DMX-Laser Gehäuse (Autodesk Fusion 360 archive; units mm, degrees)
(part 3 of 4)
sketch "Skizze25" plane through (45, 0, 0) normal (-1, 0, 0) x axis (0, -1, 0)
  line L1 (3, 60) -> (40, 60)
  line L2 (3, -2) -> (3, 60)
  line L3 (58, -2) -> (3, -2)
  line L4 (58, 8) -> (58, -2)
  line L5 (57, 8) -> (58, 8)
  line L6 (45, 55) -> (45, 20)
  line L7 (14.5116, 11) -> (14.5116, 15)
  line L8 (14.0559, 11) -> (14.5116, 11)
  line L9 (14.0559, 11.3656) -> (14.0559, 11)
  curve K1 (13.2456, 10.9345) -> (14.0559, 11.3656)
  curve K2 (12.6085, 11.1255) -> (13.2456, 10.9345)
  curve K3 (12.1583, 11.6589) -> (12.6085, 11.1255)
  curve K4 (11.9986, 12.4461) -> (12.1583, 11.6589)
  curve K5 (12.1432, 13.2333) -> (11.9986, 12.4461)
  curve K6 (12.5771, 13.7749) -> (12.1432, 13.2333)
  curve K7 (13.2237, 13.9632) -> (12.5771, 13.7749)
  curve K8 (13.6903, 13.8527) -> (13.2237, 13.9632)
  curve K9 (14.0232, 13.5648) -> (13.6903, 13.8527)
  line L10 (14.0232, 15) -> (14.0232, 13.5648)
  line L11 (14.5116, 15) -> (14.0232, 15)
  line L12 (19.4202, 12.5962) -> (16.779, 12.5962)
  line L13 (19.4202, 12.1378) -> (19.4202, 12.5962)
  line L14 (16.779, 12.1378) -> (19.4202, 12.1378)
  line L15 (16.779, 12.5962) -> (16.779, 12.1378)
  line L16 (23.3656, 15.0164) -> (23.0491, 15.0164)
  line L17 (23.3656, 11) -> (23.3656, 15.0164)
  line L18 (22.8745, 11) -> (23.3656, 11)
  line L19 (22.8745, 14.1296) -> (22.8745, 11)
  curve K10 (22.4093, 13.7913) -> (22.8745, 14.1296)
  curve K11 (21.8922, 13.5375) -> (22.4093, 13.7913)
  line L20 (21.8922, 14.0123) -> (21.8922, 13.5375)
  curve K12 (22.6126, 14.4816) -> (21.8922, 14.0123)
  curve K13 (23.0491, 15.0164) -> (22.6126, 14.4816)
  line L21 (29.9113, 11) -> (29.9113, 12.5034)
  line L22 (29.4202, 11) -> (29.9113, 11)
  line L23 (29.4202, 13.8977) -> (29.4202, 11)
  line L24 (29.8595, 13.8977) -> (29.4202, 13.8977)
  line L25 (29.8595, 13.4911) -> (29.8595, 13.8977)
  curve K14 (30.2224, 13.8336) -> (29.8595, 13.4911)
  curve K15 (30.7381, 13.9632) -> (30.2224, 13.8336)
  curve K16 (31.266, 13.8295) -> (30.7381, 13.9632)
  curve K17 (31.5566, 13.4557) -> (31.266, 13.8295)
  curve K18 (32.4516, 13.9632) -> (31.5566, 13.4557)
  curve K19 (33.1146, 13.7244) -> (32.4516, 13.9632)
  curve K20 (33.3465, 12.9891) -> (33.1146, 13.7244)
  line L26 (33.3465, 11) -> (33.3465, 12.9891)
  line L27 (32.8581, 11) -> (33.3465, 11)
  line L28 (32.8581, 12.8254) -> (32.8581, 11)
  curve K21 (32.8104, 13.2497) -> (32.8581, 12.8254)
  curve K22 (32.6371, 13.4584) -> (32.8104, 13.2497)
  curve K23 (32.3424, 13.5375) -> (32.6371, 13.4584)
  curve K24 (31.8349, 13.3342) -> (32.3424, 13.5375)
  curve K25 (31.633, 12.6835) -> (31.8349, 13.3342)
  line L29 (31.633, 11) -> (31.633, 12.6835)
  line L30 (31.1419, 11) -> (31.633, 11)
  line L31 (31.1419, 12.8827) -> (31.1419, 11)
  curve K26 (31.0218, 13.3738) -> (31.1419, 12.8827)
  curve K27 (30.6289, 13.5375) -> (31.0218, 13.3738)
  curve K28 (30.2456, 13.4284) -> (30.6289, 13.5375)
  curve K29 (29.9905, 13.1091) -> (30.2456, 13.4284)
  curve K30 (29.9113, 12.5034) -> (29.9905, 13.1091)
  curve K31 (25.0177, 11.2374) -> (25.9086, 10.9318)
  curve K32 (24.6235, 12.0477) -> (25.0177, 11.2374)
  line L32 (25.1392, 12.0914) -> (24.6235, 12.0477)
  curve K33 (25.4052, 11.5252) -> (25.1392, 12.0914)
  curve K34 (25.9086, 11.3356) -> (25.4052, 11.5252)
  curve K35 (26.5089, 11.603) -> (25.9086, 11.3356)
  curve K36 (26.7544, 12.3124) -> (26.5089, 11.603)
  curve K37 (26.5184, 12.9754) -> (26.7544, 12.3124)
  curve K38 (25.9004, 13.2183) -> (26.5184, 12.9754)
  curve K39 (25.472, 13.1105) -> (25.9004, 13.2183)
  curve K40 (25.1719, 12.8308) -> (25.472, 13.1105)
  line L33 (24.7108, 12.8909) -> (25.1719, 12.8308)
  line L34 (25.0982, 14.9454) -> (24.7108, 12.8909)
  line L35 (27.0873, 14.9454) -> (25.0982, 14.9454)
  line L36 (27.0873, 14.4761) -> (27.0873, 14.9454)
  line L37 (25.4911, 14.4761) -> (27.0873, 14.4761)
  line L38 (25.2756, 13.4011) -> (25.4911, 14.4761)
  curve K41 (26.0314, 13.6521) -> (25.2756, 13.4011)
  curve K42 (26.9154, 13.2892) -> (26.0314, 13.6521)
  curve K43 (27.2756, 12.3561) -> (26.9154, 13.2892)
  curve K44 (26.9591, 11.4175) -> (27.2756, 12.3561)
  curve K45 (25.9086, 10.9318) -> (26.9591, 11.4175)
  line L39 (34.5662, 11) -> (34.5662, 12.5034)
  line L40 (34.075, 11) -> (34.5662, 11)
  line L41 (34.075, 13.8977) -> (34.075, 11)
  line L42 (34.5143, 13.8977) -> (34.075, 13.8977)
  line L43 (34.5143, 13.4911) -> (34.5143, 13.8977)
  curve K46 (34.8772, 13.8336) -> (34.5143, 13.4911)
  curve K47 (35.3929, 13.9632) -> (34.8772, 13.8336)
  curve K48 (35.9209, 13.8295) -> (35.3929, 13.9632)
  curve K49 (36.2115, 13.4557) -> (35.9209, 13.8295)
  curve K50 (37.1064, 13.9632) -> (36.2115, 13.4557)
  curve K51 (37.7694, 13.7244) -> (37.1064, 13.9632)
  curve K52 (38.0014, 12.9891) -> (37.7694, 13.7244)
  line L44 (38.0014, 11) -> (38.0014, 12.9891)
  line L45 (37.513, 11) -> (38.0014, 11)
  line L46 (37.513, 12.8254) -> (37.513, 11)
  curve K53 (37.4652, 13.2497) -> (37.513, 12.8254)
  curve K54 (37.292, 13.4584) -> (37.4652, 13.2497)
  curve K55 (36.9973, 13.5375) -> (37.292, 13.4584)
  curve K56 (36.4898, 13.3342) -> (36.9973, 13.5375)
  curve K57 (36.2879, 12.6835) -> (36.4898, 13.3342)
  line L47 (36.2879, 11) -> (36.2879, 12.6835)
  line L48 (35.7967, 11) -> (36.2879, 11)
  line L49 (35.7967, 12.8827) -> (35.7967, 11)
  curve K58 (35.6767, 13.3738) -> (35.7967, 12.8827)
  curve K59 (35.2838, 13.5375) -> (35.6767, 13.3738)
  curve K60 (34.9004, 13.4284) -> (35.2838, 13.5375)
  curve K61 (34.6453, 13.1091) -> (34.9004, 13.4284)
  curve K62 (34.5662, 12.5034) -> (34.6453, 13.1091)
  line L50 (19.4202, 13.8104) -> (16.779, 13.8104)
  line L51 (19.4202, 13.352) -> (19.4202, 13.8104)
  line L52 (16.779, 13.352) -> (19.4202, 13.352)
  line L53 (16.779, 13.8104) -> (16.779, 13.352)
  line L54 (45.5, 37.55) -> (22.15, 37.55)
  line L55 (33.175, 39.55) -> (33.175, 37.55)
  line L56 (33.025, 39.55) -> (33.175, 39.55)
  line L57 (33.025, 48.45) -> (33.025, 39.55)
  line L58 (52.825, 39.55) -> (52.825, 48.45)
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  point P6 (22.15, 37.55)
  point P126 (22.15, 37.55)
  point P128 (33.175, 37.55)
  point P129 (33.175, 39.55)
  point P130 (33.025, 39.55)
  point P131 (33.025, 48.45)
  point P132 (52.825, 48.45)
  point P133 (52.825, 48.45)
  point P135 (33.025, 39.55)
  point P136 (38.175, 48.45)
  point P137 (47.675, 48.45)
  point P142 (52.825, 48.45)
  point P144 (33.025, 51.35)
  coincident P6 P126
  perpendicular L6 L54
  coincident L54 P128
  perpendicular L54 L55
  perpendicular L55 L56
  perpendicular L56 L57
  vertical L58
  dimension "d132" distance P128 P129 = 2
  dimension "d133" distance P129 P130 = 0.15
  dimension "d134" distance P130 P131 = 8.9
  dimension "d135" distance P131 P132 = 19.8
  dimension "d136" distance P131 P133 = 19.8
  dimension "d137" distance P131 P135 = 8.9
  dimension "d138" distance P131 P136 = 5.15
  dimension "d139" distance P133 P137 = 5.15
  dimension "d140" diameter = 2.4
  dimension "d141" diameter = 2.4
  dimension "d142" distance P131 P142 = 19.8
  dimension "d143" distance P131 P144 = 2.9
sketch "Skizze26" plane through (0, -45, 0) normal (0, -1, 0) x axis (1, 0, 0)
  line L1 (45, 55) -> (55, 55)
  line L2 (45, 20) -> (45, 55)
  line L3 (55, 20) -> (45, 20)
  line L4 (55, 55) -> (55, 20)
  line L5 (55, 54) -> (45, 54)
  line L6 (55, 43) -> (55, 54)
  line L7 (45, 43) -> (55, 43)
  line L8 (45, 54) -> (45, 43)
  point P8 (55, 43)
  point P6 (45, 54)
  horizontal L5
  vertical L6
  horizontal L7
  vertical L8
  coincident L4 P8
  coincident L2 P6
extrude "Extrusion38" add sketch "Skizze26" profile of L2 L4 L5 L6 L7 L8 along normal blind 9
extrude "Extrusion39" new body sketch "Skizze25" along normal blind 1.8
move "Verschieben6"
extrude "Extrusion40" cut of existing geometry blind -3
fillet "Abrundung8" radius 2 3
copy_paste_bodies "Körper kopieren/einfügen3"
move "Verschieben7"
move "Verschieben8"
move_face "Fläche verschieben"
move "Verschieben9" RotateAngle 180
move "Verschieben10" RotateAngle -90
copy_paste_bodies "Körper kopieren/einfügen4"
move "Verschieben11"
sketch "Skizze27" plane through (55, 0, 0) normal (1, 0, 0) x axis (0, 1, 0)
  line L1 (-51, 43) -> (-51, 54)
  line L2 (-48, 43) -> (-51, 43)
  line L3 (-45, 20) -> (-45, 40)
  line L4 (-58, 8) -> (-57, 8)
  line L5 (-58, -2) -> (-58, 8)
  line L6 (-43.3405, -2) -> (-58, -2)
  line L7 (-43.3405, 16.4) -> (-43.3405, -2)
  line L8 (-1, 16.4) -> (-43.3405, 16.4)
  line L9 (-1, 30) -> (-1, 16.4)
  line L10 (0.8579, 30) -> (-1, 30)
  line L11 (0.8579, 20) -> (0.8579, 30)
  line L12 (10, 20) -> (0.8579, 20)
  line L13 (10, 45) -> (10, 20)
  line L14 (0, 45) -> (10, 45)
  line L15 (0, 60) -> (0, 45)
  line L16 (-40, 60) -> (0, 60)
  line L17 (-51, 54) -> (-46.9282, 54)
  circle C1 centre (-22.15, 37.55) radius 11.025
  circle C2 centre (-6.65, 22.05) radius 2
  circle C3 centre (-37.65, 53.05) radius 2
  circle C4 centre (-6.65, 53.05) radius 2
  circle C5 centre (-37.65, 22.05) radius 2
  arc A1 centre (-48, 40) radius 3 clockwise from (-48, 43) to (-45, 40)
  arc A2 centre (-57, 20) radius 12 clockwise from (-45, 20) to (-57, 8)
  arc A3 centre (-40, 55) radius 5 clockwise from (-44.9487, 55.7143) to (-40, 60)
  arc A4 centre (-46.9282, 56) radius 2 clockwise from (-44.9487, 55.7143) to (-46.9282, 54)
  circle C6 centre (-37.65, 53.05) radius 2
  circle C7 centre (-37.65, 53.05) radius 1.55
  circle C8 centre (-6.65, 53.05) radius 2
  circle C9 centre (-6.65, 53.05) radius 1.55
  circle C10 centre (-37.65, 22.05) radius 2
  circle C11 centre (-37.65, 22.05) radius 1.55
  circle C12 centre (-6.65, 22.05) radius 2
  circle C13 centre (-6.65, 22.05) radius 1.55
  concentric C3 C6
  concentric C3 C7
  concentric C4 C8
  concentric C4 C9
  concentric C5 C10
  concentric C5 C11
  concentric C2 C12
  concentric C2 C13
  dimension "d156" diameter C6 = 4
  dimension "d157" diameter C7 = 3.1
  dimension "d158" diameter C8 = 4
  dimension "d159" diameter C9 = 3.1
  dimension "d160" diameter C10 = 4
  dimension "d161" diameter C11 = 3.1
  dimension "d162" diameter C12 = 4
  dimension "d163" diameter C13 = 3.1
extrude "Extrusion41" add sketch "Skizze27" profile of C2 C3 C4 C5 C6 C7 C8 C9 C10 C11 C12 C13 against normal blind 10
sketch "Skizze28" plane through (0, 10, 0) normal (0, 1, 0) x axis (-1, 0, 0)
  line L1 (-45.18, 30) -> (-45.18, -2)
  line L2 (-43.3, 30) -> (-45.18, 30)
  line L3 (-43.3, 1.4) -> (-43.3, 30)
  line L4 (-1, 1.4) -> (-43.3, 1.4)
  line L5 (-1, -2) -> (-1, 1.4)
  line L6 (13, -2) -> (-1, -2)
  line L7 (13, 8) -> (13, -2)
  line L8 (12, 8) -> (13, 8)
  line L9 (0, 41.3962) -> (0, 20)
  line L10 (-45, 60) -> (-3.4189, 46.1396)
  line L11 (-55, 60) -> (-45, 60)
  line L12 (-55, 45) -> (-55, 60)
  line L13 (-55, 20) -> (-55, 45)
  line L14 (-45.8579, 20) -> (-55, 20)
  line L15 (-45.8579, 8) -> (-45.8579, 20)
  line L16 (-45.8579, -2) -> (-45.8579, 8)
  line L17 (-45.18, -2) -> (-45.8579, -2)
  arc A1 centre (12, 20) radius 12 clockwise from (12, 8) to (0, 20)
  arc A2 centre (-5, 41.3962) radius 5 clockwise from (-3.4189, 46.1396) to (0, 41.3962)
  circle C1 centre (-37.65, 7.05) radius 2
  circle C2 centre (-6.65, 38.05) radius 2
  circle C3 centre (-37.65, 38.05) radius 2
  circle C4 centre (-6.65, 7.05) radius 2
  circle C5 centre (-22.15, 22.55) radius 11.025
  circle C6 centre (-37.65, 38.05) radius 2
  circle C7 centre (-37.65, 38.05) radius 1.55
  circle C8 centre (-6.65, 38.05) radius 2
  circle C9 centre (-6.65, 38.05) radius 1.55
  circle C10 centre (-37.65, 7.05) radius 2
  circle C11 centre (-37.65, 7.05) radius 1.55
  circle C12 centre (-6.65, 7.05) radius 2
  circle C13 centre (-6.65, 7.05) radius 1.55
  concentric C3 C6
  concentric C3 C7
  concentric C2 C8
  concentric C2 C9
  concentric C1 C10
  concentric C1 C11
  concentric C4 C12
  concentric C4 C13
  dimension "d166" diameter C6 = 4
  dimension "d167" diameter C7 = 3.1
  dimension "d168" diameter C8 = 4
  dimension "d169" diameter C9 = 3.1
  dimension "d170" diameter C10 = 4
  dimension "d171" diameter C11 = 3.1
  dimension "d172" diameter C12 = 4
  dimension "d173" diameter C13 = 3.1
extrude "Extrusion42" add sketch "Skizze28" profile of C1 C2 C3 C4 C6 C7 C8 C9 C10 C11 C12 C13 against normal blind 10
move "Verschieben12"
move "Verschieben13"
move "Verschieben14"
sketch "Skizze29" plane through (0, 0, 0) normal (0, -1, 0) x axis (1, 0, 0)
  line L1 (0, 20) -> (0, 41.3962)
  line L2 (-13, 8) -> (-12, 8)
  line L3 (-13, -2) -> (-13, 8)
  line L4 (42, -2) -> (-13, -2)
  line L5 (42, 59) -> (42, -2)
  line L6 (3.4189, 46.1396) -> (42, 59)
  circle C1 centre (37.65, 7.05) radius 1.55
  circle C2 centre (37.65, 38.05) radius 1.55
  circle C3 centre (6.65, 7.05) radius 1.55
  circle C4 centre (6.65, 38.05) radius 1.55
  arc A1 centre (5, 41.3962) radius 5 clockwise from (0, 41.3962) to (3.4189, 46.1396)
  arc A2 centre (-12, 20) radius 12 clockwise from (0, 20) to (-12, 8)
  circle C5 centre (22.15, 22.55) radius 11.025
  circle C6 centre (37.65, 38.05) radius 3.5
  concentric C2 C6
  dimension "d176" diameter C6 = 7
extrude "Extrusion43" cut sketch "Skizze29" profile of C2 C6 along normal blind 5
sketch "Skizze30" plane through (45, 0, 0) normal (-1, 0, 0) x axis (0, -1, 0)
  line L1 (49.825, 51.35) -> (30.025, 51.35)
  line L2 (49.825, 43) -> (49.825, 51.35)
  line L3 (51, 43) -> (49.825, 43)
  line L4 (51, 54) -> (51, 43)
  line L5 (46.9282, 54) -> (51, 54)
  line L6 (3, 60) -> (40, 60)
  line L7 (3, -2) -> (3, 60)
  line L8 (58, -2) -> (3, -2)
  line L9 (58, 8) -> (58, -2)
  line L10 (57, 8) -> (58, 8)
  line L11 (45, 39.55) -> (45, 20)
  line L12 (32.9921, 39.55) -> (45, 39.55)
  line L13 (30.025, 51.35) -> (30.025, 45.2659)
  line L14 (14.5116, 11) -> (14.5116, 15)
  line L15 (14.0559, 11) -> (14.5116, 11)
  line L16 (14.0559, 11.3656) -> (14.0559, 11)
  curve K1 (13.2456, 10.9345) -> (14.0559, 11.3656)
  curve K2 (12.6085, 11.1255) -> (13.2456, 10.9345)
  curve K3 (12.1583, 11.6589) -> (12.6085, 11.1255)
  curve K4 (11.9986, 12.4461) -> (12.1583, 11.6589)
  curve K5 (12.1432, 13.2333) -> (11.9986, 12.4461)
  curve K6 (12.5771, 13.7749) -> (12.1432, 13.2333)
  curve K7 (13.2237, 13.9632) -> (12.5771, 13.7749)
  curve K8 (13.6903, 13.8527) -> (13.2237, 13.9632)
  curve K9 (14.0232, 13.5648) -> (13.6903, 13.8527)
  line L17 (14.0232, 15) -> (14.0232, 13.5648)
  line L18 (14.5116, 15) -> (14.0232, 15)
  line L19 (19.4202, 12.5962) -> (16.779, 12.5962)
  line L20 (19.4202, 12.1378) -> (19.4202, 12.5962)
  line L21 (16.779, 12.1378) -> (19.4202, 12.1378)
  line L22 (16.779, 12.5962) -> (16.779, 12.1378)
  line L23 (23.3656, 15.0164) -> (23.0491, 15.0164)
  line L24 (23.3656, 11) -> (23.3656, 15.0164)
  line L25 (22.8745, 11) -> (23.3656, 11)
  line L26 (22.8745, 14.1296) -> (22.8745, 11)
  curve K10 (22.4093, 13.7913) -> (22.8745, 14.1296)
  curve K11 (21.8922, 13.5375) -> (22.4093, 13.7913)
  line L27 (21.8922, 14.0123) -> (21.8922, 13.5375)
  curve K12 (22.6126, 14.4816) -> (21.8922, 14.0123)
  curve K13 (23.0491, 15.0164) -> (22.6126, 14.4816)
  line L28 (29.9113, 11) -> (29.9113, 12.5034)
  line L29 (29.4202, 11) -> (29.9113, 11)
  line L30 (29.4202, 13.8977) -> (29.4202, 11)
  line L31 (29.8595, 13.8977) -> (29.4202, 13.8977)
  line L32 (29.8595, 13.4911) -> (29.8595, 13.8977)
  curve K14 (30.2224, 13.8336) -> (29.8595, 13.4911)
  curve K15 (30.7381, 13.9632) -> (30.2224, 13.8336)
  curve K16 (31.266, 13.8295) -> (30.7381, 13.9632)
  curve K17 (31.5566, 13.4557) -> (31.266, 13.8295)
  curve K18 (32.4516, 13.9632) -> (31.5566, 13.4557)
  curve K19 (33.1146, 13.7244) -> (32.4516, 13.9632)
  curve K20 (33.3465, 12.9891) -> (33.1146, 13.7244)
  line L33 (33.3465, 11) -> (33.3465, 12.9891)
  line L34 (32.8581, 11) -> (33.3465, 11)
  line L35 (32.8581, 12.8254) -> (32.8581, 11)
  curve K21 (32.8104, 13.2497) -> (32.8581, 12.8254)
  curve K22 (32.6371, 13.4584) -> (32.8104, 13.2497)
  curve K23 (32.3424, 13.5375) -> (32.6371, 13.4584)
  curve K24 (31.8349, 13.3342) -> (32.3424, 13.5375)
  curve K25 (31.633, 12.6835) -> (31.8349, 13.3342)
  line L36 (31.633, 11) -> (31.633, 12.6835)
  line L37 (31.1419, 11) -> (31.633, 11)
  line L38 (31.1419, 12.8827) -> (31.1419, 11)
  curve K26 (31.0218, 13.3738) -> (31.1419, 12.8827)
  curve K27 (30.6289, 13.5375) -> (31.0218, 13.3738)
  curve K28 (30.2456, 13.4284) -> (30.6289, 13.5375)
  curve K29 (29.9905, 13.1091) -> (30.2456, 13.4284)
  curve K30 (29.9113, 12.5034) -> (29.9905, 13.1091)
  curve K31 (25.0177, 11.2374) -> (25.9086, 10.9318)
  curve K32 (24.6235, 12.0477) -> (25.0177, 11.2374)
  line L39 (25.1392, 12.0914) -> (24.6235, 12.0477)
  curve K33 (25.4052, 11.5252) -> (25.1392, 12.0914)
  curve K34 (25.9086, 11.3356) -> (25.4052, 11.5252)
  curve K35 (26.5089, 11.603) -> (25.9086, 11.3356)
  curve K36 (26.7544, 12.3124) -> (26.5089, 11.603)
  curve K37 (26.5184, 12.9754) -> (26.7544, 12.3124)
  curve K38 (25.9004, 13.2183) -> (26.5184, 12.9754)
  curve K39 (25.472, 13.1105) -> (25.9004, 13.2183)
  curve K40 (25.1719, 12.8308) -> (25.472, 13.1105)
  line L40 (24.7108, 12.8909) -> (25.1719, 12.8308)
  line L41 (25.0982, 14.9454) -> (24.7108, 12.8909)
  line L42 (27.0873, 14.9454) -> (25.0982, 14.9454)
  line L43 (27.0873, 14.4761) -> (27.0873, 14.9454)
  line L44 (25.4911, 14.4761) -> (27.0873, 14.4761)
  line L45 (25.2756, 13.4011) -> (25.4911, 14.4761)
  curve K41 (26.0314, 13.6521) -> (25.2756, 13.4011)
  curve K42 (26.9154, 13.2892) -> (26.0314, 13.6521)
  curve K43 (27.2756, 12.3561) -> (26.9154, 13.2892)
  curve K44 (26.9591, 11.4175) -> (27.2756, 12.3561)
  curve K45 (25.9086, 10.9318) -> (26.9591, 11.4175)
  line L46 (34.5662, 11) -> (34.5662, 12.5034)
  line L47 (34.075, 11) -> (34.5662, 11)
  line L48 (34.075, 13.8977) -> (34.075, 11)
  line L49 (34.5143, 13.8977) -> (34.075, 13.8977)
  line L50 (34.5143, 13.4911) -> (34.5143, 13.8977)
  curve K46 (34.8772, 13.8336) -> (34.5143, 13.4911)
  curve K47 (35.3929, 13.9632) -> (34.8772, 13.8336)
  curve K48 (35.9209, 13.8295) -> (35.3929, 13.9632)
  curve K49 (36.2115, 13.4557) -> (35.9209, 13.8295)
  curve K50 (37.1064, 13.9632) -> (36.2115, 13.4557)
  curve K51 (37.7694, 13.7244) -> (37.1064, 13.9632)
  curve K52 (38.0014, 12.9891) -> (37.7694, 13.7244)
  line L51 (38.0014, 11) -> (38.0014, 12.9891)
  line L52 (37.513, 11) -> (38.0014, 11)
  line L53 (37.513, 12.8254) -> (37.513, 11)
  curve K53 (37.4652, 13.2497) -> (37.513, 12.8254)
  curve K54 (37.292, 13.4584) -> (37.4652, 13.2497)
  curve K55 (36.9973, 13.5375) -> (37.292, 13.4584)
  curve K56 (36.4898, 13.3342) -> (36.9973, 13.5375)
  curve K57 (36.2879, 12.6835) -> (36.4898, 13.3342)
  line L54 (36.2879, 11) -> (36.2879, 12.6835)
  line L55 (35.7967, 11) -> (36.2879, 11)
  line L56 (35.7967, 12.8827) -> (35.7967, 11)
  curve K58 (35.6767, 13.3738) -> (35.7967, 12.8827)
  curve K59 (35.2838, 13.5375) -> (35.6767, 13.3738)
  curve K60 (34.9004, 13.4284) -> (35.2838, 13.5375)
  curve K61 (34.6453, 13.1091) -> (34.9004, 13.4284)
  curve K62 (34.5662, 12.5034) -> (34.6453, 13.1091)
  line L57 (19.4202, 13.8104) -> (16.779, 13.8104)
  line L58 (19.4202, 13.352) -> (19.4202, 13.8104)
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  dimension "d179" diameter = 7
extrude "Extrusion44" cut sketch "Skizze30" along normal blind 5
move "Verschieben15" TranslateX 0 TranslateY 0.025 TranslateZ 0
combine "Kombinieren2"
extrude "Extrusion46" cut of existing geometry blind -2
extrude "Extrusion47" cut of existing geometry blind -2
sketch "Skizze32" plane through (29, 0, 0) normal (-1, 0, 0) x axis (0, -1, 0)
  line L1 (22.15, 33.05) -> (22.15, 42.05)
  line L2 (22.15, 22.546) -> (22.15, 37.55)
  line L3 (16.2, 22.546) -> (22.15, 22.546)
  arc A1 centre (22.15, 37.55) radius 4.5 clockwise from (22.15, 42.05) to (22.15, 33.05)
  point P4 (22.15, 37.55)
  point P5 (22.15, 37.55)
  coincident P4 P5
  parallel L1 L2
  perpendicular L2 L3
extrude "Extrusion48" cut of existing geometry blind -2
extrude "Extrusion49" cut sketch "Skizze32" profile of A1 L1 L2 against normal blind 2
sketch "Skizze33" plane through (0, -14, 0) normal (0, -1, 0) x axis (1, 0, 0)
  line L1 (22.15, 20.05) -> (22.15, 22.55)
  line L2 (22.15, 24.25) -> (22.15, 20.05)
  line L3 (24.8486, 26) -> (18, 26)
  line L4 (24.8486, 24.25) -> (24.8486, 26)
  line L5 (18, 24.25) -> (24.8486, 24.25)
  line L6 (18, 26) -> (18, 24.25)
  circle C1 centre (22.15, 22.55) radius 2.5
  point P2 (22.15, 22.55)
  point P3 (22.15, 22.55)
  point P4 (22.15, 20.05)
  point P5 (22.15, 24.25)
  coincident P2 P3
  coincident C1 P4
  vertical L1
  parallel L1 L2
  horizontal L3
  vertical L4
  horizontal L5
  vertical L6
  dimension "d200" distance P4 P5 = 4.2
extrude "Extrusion50" cut sketch "Skizze33" profile of C1 L5 against normal blind 24
sketch "Skizze34" plane through (31, 0, 0) normal (-1, 0, 0) x axis (0, -1, 0)
  line L1 (22.15, 35.05) -> (22.15, 37.55)
  line L2 (22.15, 39.25) -> (22.15, 35.05)
  line L3 (24.8432, 41) -> (19, 41)
  line L4 (24.8432, 39.25) -> (24.8432, 41)
  line L5 (19, 39.25) -> (24.8432, 39.25)
  line L6 (19, 41) -> (19, 39.25)
  circle C1 centre (22.15, 37.55) radius 2.5
  point P2 (22.15, 37.55)
  point P3 (22.15, 37.55)
  point P4 (22.15, 35.05)
  point P5 (22.15, 39.25)
  coincident P2 P3
  coincident C1 P4
  vertical L1
  parallel L1 L2
  horizontal L3
  vertical L4
  horizontal L5
  vertical L6
  dimension "d203" distance P4 P5 = 4.2
extrude "Extrusion51" cut sketch "Skizze34" profile of C1 L5 against normal blind 24
sketch "Skizze35" plane through (31, 0, 0) normal (1, 0, 0) x axis (0, 1, 0)
  line L1 (-22.15, 35.05) -> (-22.15, 40.05)
  line L2 (-22.15, 35.05) -> (-22.15, 37.55)
  line L3 (-22.15, 39.25) -> (-22.15, 35.05)
  line L4 (-20.317, 39.25) -> (-22.15, 39.25)
  line L5 (-24, 39.25) -> (-22.15, 39.25)
  arc A1 centre (-22.15, 37.55) radius 2.5 clockwise from (-22.15, 40.05) to (-22.15, 35.05)
  circle C1 centre (-22.15, 37.55) radius 2.5
  point P4 (-22.15, 37.55)
  point P5 (-22.15, 37.55)
  point P3 (-22.15, 35.05)
  point P6 (-22.15, 35.05)
  point P8 (-20.317, 39.25)
  point P7 (-22.15, 39.25)
  coincident P4 P5
  coincident P3 P6
  parallel L1 L3
  coincident A1 P8
  perpendicular L1 L4
  perpendicular L1 L5
  concentric A1 C1
  dimension "d206" distance P6 P7 = 4.2
extrude "Extrusion52" add sketch "Skizze35" profile of L1 A1 L4 L5 C1 along normal blind 12
sketch "Skizze36" plane through (0, -14.15, 0) normal (0, 1, 0) x axis (-1, 0, 0)
  line L1 (-24.65, 22.55) -> (-19.65, 22.55)
  line L2 (-22.15, 20.05) -> (-22.15, 22.55)
  line L3 (-22.15, 24.25) -> (-22.15, 20.05)
  line L4 (-20.317, 24.25) -> (-22.15, 24.25)
  line L5 (-23.983, 24.25) -> (-22.15, 24.25)
  arc A1 centre (-22.15, 22.55) radius 2.5 clockwise from (-19.65, 22.55) to (-24.65, 22.55)
  circle C1 centre (-22.15, 22.55) radius 2.5
  point P2 (-19.65, 22.55)
  point P5 (-22.15, 22.55)
  point P6 (-22.15, 22.55)
  point P7 (-22.15, 20.05)
  point P9 (-20.317, 24.25)
  point P10 (-23.983, 24.25)
  point P8 (-22.15, 24.25)
  concentric A1 C1
  coincident P2 C1
  coincident P5 P6
  midpoint A1 P7
  parallel L2 L3
  coincident C1 P9
  perpendicular L3 L4
  coincident C1 P10
  perpendicular L3 L5
  dimension "d209" distance P7 P8 = 4.2
extrude "Extrusion53" add sketch "Skizze36" profile of C1 L4 L5 along normal blind 12
sketch "Skizze37" plane through (43, 0, 0) normal (1, 0, 0) x axis (0, 1, 0)
  line L1 (-20.317, 39.25) -> (-23.983, 39.25)
  line L2 (-34.15, 39.55) -> (-26.1811, 39.55)
  line L3 (-34.15, 35.55) -> (-34.15, 39.55)
  line L4 (-26.1811, 35.55) -> (-34.15, 35.55)
  line L5 (-14.65, 35.55) -> (-18.1189, 35.55)
  line L6 (-14.65, 39.55) -> (-14.65, 35.55)
  line L7 (-18.1189, 39.55) -> (-14.65, 39.55)
  line L8 (-19.5, 39.25) -> (-23.7816, 39.25)
  line L9 (-24.8, 39.25) -> (-19.5, 39.25)
  arc A1 centre (-22.15, 37.55) radius 2.5 clockwise from (-20.317, 39.25) to (-23.983, 39.25)
  arc A2 centre (-22.15, 37.55) radius 4.5 clockwise from (-26.1811, 39.55) to (-18.1189, 39.55)
  arc A3 centre (-22.15, 37.55) radius 4.5 clockwise from (-18.1189, 35.55) to (-26.1811, 35.55)
  circle C1 centre (-22.15, 37.55) radius 2.575
  point P13 (-23.7816, 39.25)
  coincident L1 P13
  parallel L1 L9
  concentric A1 C1
  dimension "d212" diameter C1 = 5.15
extrude "Extrusion54" cut sketch "Skizze37" profile of A1 L8 L9 C1 against normal blind 12
sketch "Skizze38" plane through (0, -2.15, 0) normal (0, 1, 0) x axis (-1, 0, 0)
  line L1 (-20.317, 24.25) -> (-23.983, 24.25)
  line L2 (-20.15, 34.55) -> (-20.15, 26.5811)
  line L3 (-24.15, 34.55) -> (-20.15, 34.55)
  line L4 (-24.15, 26.5811) -> (-24.15, 34.55)
  line L5 (-24.15, 15.05) -> (-24.15, 18.5189)
  line L6 (-20.15, 15.05) -> (-24.15, 15.05)
  line L7 (-20.15, 18.5189) -> (-20.15, 15.05)
  line L8 (-19.2431, 24.25) -> (-22.9895, 24.25)
  line L9 (-25, 24.25) -> (-19.2431, 24.25)
  arc A1 centre (-22.15, 22.55) radius 2.5 clockwise from (-20.317, 24.25) to (-23.983, 24.25)
  arc A2 centre (-22.15, 22.55) radius 4.5 clockwise from (-20.15, 26.5811) to (-20.15, 18.5189)
  arc A3 centre (-22.15, 22.55) radius 4.5 clockwise from (-24.15, 18.5189) to (-24.15, 26.5811)
  circle C1 centre (-22.15, 22.55) radius 2.575
  point P13 (-22.9895, 24.25)
  coincident L1 P13
  parallel L1 L9
  concentric A1 C1
  dimension "d215" diameter C1 = 5.15
extrude "Extrusion55" cut sketch "Skizze38" profile of A1 L8 L9 C1 against normal blind 12
sketch "Skizze39" plane through (43, 0, 0) normal (1, 0, 0) x axis (0, 1, 0)
  line L1 (-34.15, 39.55) -> (-26.1811, 39.55)
  line L2 (-34.15, 35.55) -> (-34.15, 39.55)
  line L3 (-26.1811, 35.55) -> (-34.15, 35.55)
  line L4 (-14.65, 35.55) -> (-18.1189, 35.55)
  line L5 (-14.65, 39.55) -> (-14.65, 35.55)
  line L6 (-18.1189, 39.55) -> (-14.65, 39.55)
  line L7 (-20.2159, 39.25) -> (-24.0841, 39.25)
  line L8 (-19.8, 39.25) -> (-24.3972, 39.25)
  line L9 (-19.8, 39.35) -> (-24.3972, 39.35)
  arc A1 centre (-22.15, 37.55) radius 4.5 clockwise from (-26.1811, 39.55) to (-18.1189, 39.55)
  arc A2 centre (-22.15, 37.55) radius 4.5 clockwise from (-18.1189, 35.55) to (-26.1811, 35.55)
  arc A3 centre (-22.15, 37.55) radius 2.575 clockwise from (-20.2159, 39.25) to (-24.0841, 39.25)
  circle C1 centre (-22.15, 37.55) radius 2.6
  concentric A1 C1
  parallel L7 L8
  dimension "d218" diameter C1 = 5.2
  dimension "d219" = -0.1
extrude "Extrusion56" cut sketch "Skizze39" profile of L7 A3 C1 L8 L9 against normal blind 12
sketch "Skizze40" plane through (43, 0, 0) normal (1, 0, 0) x axis (0, 1, 0)
  line L1 (-20.2738, 39.35) -> (-24.0262, 39.35)
  line L2 (-34.15, 39.55) -> (-26.1811, 39.55)
  line L3 (-34.15, 35.55) -> (-34.15, 39.55)
  line L4 (-26.1811, 35.55) -> (-34.15, 35.55)
  line L5 (-14.65, 35.55) -> (-18.1189, 35.55)
  line L6 (-14.65, 39.55) -> (-14.65, 35.55)
  line L7 (-18.1189, 39.55) -> (-14.65, 39.55)
  line L8 (-20, 39.35) -> (-24.364, 39.35)
  line L9 (-20, 39.45) -> (-24.364, 39.45)
  arc A1 centre (-22.15, 37.55) radius 2.6 clockwise from (-20.2738, 39.35) to (-24.0262, 39.35)
  arc A2 centre (-22.15, 37.55) radius 4.5 clockwise from (-26.1811, 39.55) to (-18.1189, 39.55)
  arc A3 centre (-22.15, 37.55) radius 4.5 clockwise from (-18.1189, 35.55) to (-26.1811, 35.55)
  circle C1 centre (-22.15, 37.55) radius 2.6
  parallel L1 L8
  concentric A1 C1
  dimension "d222" = -0.1
extrude "Extrusion57" cut sketch "Skizze40" profile of L1 L8 L9 C1 against normal blind 12
extrude "Extrusion58" cut of existing geometry blind -20
extrude "Extrusion59" cut of existing geometry blind -20
sketch "Skizze41" plane through (43, 0, 0) normal (1, 0, 0) x axis (0, 1, 0)
  line L1 (-34.15, 39.55) -> (-26.1811, 39.55)
  line L2 (-34.15, 35.55) -> (-34.15, 39.55)
  line L3 (-26.1811, 35.55) -> (-34.15, 35.55)
  line L4 (-20.3752, 39.45) -> (-23.9248, 39.45)
  line L5 (-20.3752, 39.45) -> (-23.9248, 39.45)
  line L6 (-20.3556, 39.5) -> (-23.9444, 39.5)
  line L7 (-20.3362, 39.55) -> (-23.9638, 39.55)
  arc A1 centre (-22.15, 37.55) radius 4.5 clockwise from (-26.1811, 39.55) to (-26.1811, 35.55)
  arc A2 centre (-22.15, 37.55) radius 2.6 clockwise from (-20.3752, 39.45) to (-23.9248, 39.45)
  arc A3 centre (-22.15, 37.55) radius 2.6 clockwise from (-20.3752, 39.45) to (-23.9248, 39.45)
  arc A4 centre (-22.15, 37.55) radius 2.65 clockwise from (-20.3556, 39.5) to (-23.9444, 39.5)
  arc A5 centre (-22.15, 37.55) radius 2.7 clockwise from (-20.3362, 39.55) to (-23.9638, 39.55)
  point P7 (-23.9248, 39.45)
  point P10 (-23.9248, 39.45)
  point P8 (-20.3752, 39.45)
  point P11 (-20.3752, 39.45)
  concentric A1 A3
  coincident P7 P10
  coincident P8 P11
  dimension "d229" = 0.05
  dimension "d232" = -0.1
extrude "Extrusion60" cut sketch "Skizze41" profile of A2 L4 A3 L5 A4 L6 against normal blind 12
extrude "Extrusion61" cut sketch "Skizze41" profile of A2 L4 A3 L5 A4 L6 L7 A5 against normal blind 12
fillet "Abrundung9" radius 1
sketch "Skizze42" plane through (0, 0, 0) normal (0, -1, 0) x axis (1, 0, 0)
  line L1 (24.15, 50.35) -> (24.15, 33.3921)
  line L2 (35.95, 50.35) -> (24.15, 50.35)
  line L3 (35.95, 41.1094) -> (35.95, 50.35)
  line L4 (35.95, 30.55) -> (35.95, 34.9906)
  line L5 (29.7362, 30.55) -> (35.95, 30.55)
  line L6 (0, 20) -> (0, 41.3962)
  line L7 (-13, 8) -> (-12, 8)
  line L8 (-13, -2) -> (-13, 8)
  line L9 (42, -2) -> (-13, -2)
  line L10 (42, 59) -> (42, -2)
  line L11 (3.4189, 46.1396) -> (42, 59)
  arc A1 centre (37.65, 38.05) radius 3.5 clockwise from (35.95, 34.9906) to (35.95, 41.1094)
  arc A2 centre (22.15, 22.55) radius 11.025 clockwise from (29.7362, 30.55) to (24.15, 33.3921)
  arc A3 centre (5, 41.3962) radius 5 clockwise from (0, 41.3962) to (3.4189, 46.1396)
  arc A4 centre (-12, 20) radius 12 clockwise from (0, 20) to (-12, 8)
  circle C1 centre (6.65, 38.05) radius 1.55
  circle C2 centre (6.65, 7.05) radius 1.55
  circle C3 centre (37.65, 38.05) radius 1.55
  circle C4 centre (37.65, 7.05) radius 1.55
  circle C5 centre (37.65, 38.05) radius 3.5
  circle C6 centre (6.65, 38.05) radius 3.5
  circle C7 centre (6.65, 7.05) radius 3.5
  circle C8 centre (37.65, 7.05) radius 3.5
  concentric A1 C5
  concentric C1 C6
  concentric C2 C7
  concentric C4 C8
  dimension "d237" diameter C6 = 7
  dimension "d238" diameter C7 = 7
  dimension "d239" diameter C8 = 7
extrude "Extrusion62" cut sketch "Skizze42" profile of A1 C1 C2 C3 C4 C5 C6 C7 C8 against normal blind 3
sketch "Skizze43" plane through (45, 0, 0) normal (-1, 0, 0) x axis (0, -1, 0)
  line L1 (49.825, 51.35) -> (40.7094, 51.35)
  line L2 (49.825, 43) -> (49.825, 51.35)
  line L3 (51, 43) -> (49.825, 43)
  line L4 (51, 54) -> (51, 43)
  line L5 (46.9282, 54) -> (51, 54)
  line L6 (3, 60) -> (40, 60)
  line L7 (3, -2) -> (3, 60)
  line L8 (58, -2) -> (3, -2)
  line L9 (58, 8) -> (58, -2)
  line L10 (57, 8) -> (58, 8)
  line L11 (45, 39.55) -> (45, 20)
  line L12 (32.9921, 39.55) -> (45, 39.55)
  line L13 (30.025, 51.35) -> (30.025, 45.2659)
  line L14 (34.5906, 51.35) -> (30.025, 51.35)
  line L15 (14.5116, 11) -> (14.5116, 15)
  line L16 (14.0559, 11) -> (14.5116, 11)
  line L17 (14.0559, 11.3656) -> (14.0559, 11)
  curve K1 (13.2456, 10.9345) -> (14.0559, 11.3656)
  curve K2 (12.6085, 11.1255) -> (13.2456, 10.9345)
  curve K3 (12.1583, 11.6589) -> (12.6085, 11.1255)
  curve K4 (11.9986, 12.4461) -> (12.1583, 11.6589)
  curve K5 (12.1432, 13.2333) -> (11.9986, 12.4461)
  curve K6 (12.5771, 13.7749) -> (12.1432, 13.2333)
  curve K7 (13.2237, 13.9632) -> (12.5771, 13.7749)
  curve K8 (13.6903, 13.8527) -> (13.2237, 13.9632)
  curve K9 (14.0232, 13.5648) -> (13.6903, 13.8527)
  line L18 (14.0232, 15) -> (14.0232, 13.5648)
  line L19 (14.5116, 15) -> (14.0232, 15)
  line L20 (19.4202, 12.5962) -> (16.779, 12.5962)
  line L21 (19.4202, 12.1378) -> (19.4202, 12.5962)
  line L22 (16.779, 12.1378) -> (19.4202, 12.1378)
  line L23 (16.779, 12.5962) -> (16.779, 12.1378)
  line L24 (23.3656, 15.0164) -> (23.0491, 15.0164)
  line L25 (23.3656, 11) -> (23.3656, 15.0164)
  line L26 (22.8745, 11) -> (23.3656, 11)
  line L27 (22.8745, 14.1296) -> (22.8745, 11)
  curve K10 (22.4093, 13.7913) -> (22.8745, 14.1296)
  curve K11 (21.8922, 13.5375) -> (22.4093, 13.7913)
  line L28 (21.8922, 14.0123) -> (21.8922, 13.5375)
  curve K12 (22.6126, 14.4816) -> (21.8922, 14.0123)
  curve K13 (23.0491, 15.0164) -> (22.6126, 14.4816)
  line L29 (29.9113, 11) -> (29.9113, 12.5034)
  line L30 (29.4202, 11) -> (29.9113, 11)
  line L31 (29.4202, 13.8977) -> (29.4202, 11)
  line L32 (29.8595, 13.8977) -> (29.4202, 13.8977)
  line L33 (29.8595, 13.4911) -> (29.8595, 13.8977)
  curve K14 (30.2224, 13.8336) -> (29.8595, 13.4911)
  curve K15 (30.7381, 13.9632) -> (30.2224, 13.8336)
  curve K16 (31.266, 13.8295) -> (30.7381, 13.9632)
  curve K17 (31.5566, 13.4557) -> (31.266, 13.8295)
  curve K18 (32.4516, 13.9632) -> (31.5566, 13.4557)
  curve K19 (33.1146, 13.7244) -> (32.4516, 13.9632)
  curve K20 (33.3465, 12.9891) -> (33.1146, 13.7244)
  line L34 (33.3465, 11) -> (33.3465, 12.9891)
  line L35 (32.8581, 11) -> (33.3465, 11)
  line L36 (32.8581, 12.8254) -> (32.8581, 11)
  curve K21 (32.8104, 13.2497) -> (32.8581, 12.8254)
  curve K22 (32.6371, 13.4584) -> (32.8104, 13.2497)
  curve K23 (32.3424, 13.5375) -> (32.6371, 13.4584)
  curve K24 (31.8349, 13.3342) -> (32.3424, 13.5375)
  curve K25 (31.633, 12.6835) -> (31.8349, 13.3342)
  line L37 (31.633, 11) -> (31.633, 12.6835)
  line L38 (31.1419, 11) -> (31.633, 11)
  line L39 (31.1419, 12.8827) -> (31.1419, 11)
  curve K26 (31.0218, 13.3738) -> (31.1419, 12.8827)
  curve K27 (30.6289, 13.5375) -> (31.0218, 13.3738)
  curve K28 (30.2456, 13.4284) -> (30.6289, 13.5375)
  curve K29 (29.9905, 13.1091) -> (30.2456, 13.4284)
  curve K30 (29.9113, 12.5034) -> (29.9905, 13.1091)
  curve K31 (25.0177, 11.2374) -> (25.9086, 10.9318)
  curve K32 (24.6235, 12.0477) -> (25.0177, 11.2374)
  line L40 (25.1392, 12.0914) -> (24.6235, 12.0477)
  curve K33 (25.4052, 11.5252) -> (25.1392, 12.0914)
  curve K34 (25.9086, 11.3356) -> (25.4052, 11.5252)
  curve K35 (26.5089, 11.603) -> (25.9086, 11.3356)
  curve K36 (26.7544, 12.3124) -> (26.5089, 11.603)
  curve K37 (26.5184, 12.9754) -> (26.7544, 12.3124)
  curve K38 (25.9004, 13.2183) -> (26.5184, 12.9754)
  curve K39 (25.472, 13.1105) -> (25.9004, 13.2183)
  curve K40 (25.1719, 12.8308) -> (25.472, 13.1105)
  line L41 (24.7108, 12.8909) -> (25.1719, 12.8308)
  line L42 (25.0982, 14.9454) -> (24.7108, 12.8909)
  line L43 (27.0873, 14.9454) -> (25.0982, 14.9454)
  line L44 (27.0873, 14.4761) -> (27.0873, 14.9454)
  line L45 (25.4911, 14.4761) -> (27.0873, 14.4761)
  line L46 (25.2756, 13.4011) -> (25.4911, 14.4761)
  curve K41 (26.0314, 13.6521) -> (25.2756, 13.4011)
  curve K42 (26.9154, 13.2892) -> (26.0314, 13.6521)
  curve K43 (27.2756, 12.3561) -> (26.9154, 13.2892)
  curve K44 (26.9591, 11.4175) -> (27.2756, 12.3561)
  curve K45 (25.9086, 10.9318) -> (26.9591, 11.4175)
  line L47 (34.5662, 11) -> (34.5662, 12.5034)
  line L48 (34.075, 11) -> (34.5662, 11)
  line L49 (34.075, 13.8977) -> (34.075, 11)
  line L50 (34.5143, 13.8977) -> (34.075, 13.8977)
  line L51 (34.5143, 13.4911) -> (34.5143, 13.8977)
  curve K46 (34.8772, 13.8336) -> (34.5143, 13.4911)
  curve K47 (35.3929, 13.9632) -> (34.8772, 13.8336)
  curve K48 (35.9209, 13.8295) -> (35.3929, 13.9632)
  curve K49 (36.2115, 13.4557) -> (35.9209, 13.8295)
  curve K50 (37.1064, 13.9632) -> (36.2115, 13.4557)
  curve K51 (37.7694, 13.7244) -> (37.1064, 13.9632)
  curve K52 (38.0014, 12.9891) -> (37.7694, 13.7244)
  line L52 (38.0014, 11) -> (38.0014, 12.9891)
  line L53 (37.513, 11) -> (38.0014, 11)
  line L54 (37.513, 12.8254) -> (37.513, 11)
  curve K53 (37.4652, 13.2497) -> (37.513, 12.8254)
  curve K54 (37.292, 13.4584) -> (37.4652, 13.2497)
  curve K55 (36.9973, 13.5375) -> (37.292, 13.4584)
  curve K56 (36.4898, 13.3342) -> (36.9973, 13.5375)
  curve K57 (36.2879, 12.6835) -> (36.4898, 13.3342)
  line L55 (36.2879, 11) -> (36.2879, 12.6835)
  line L56 (35.7967, 11) -> (36.2879, 11)
  line L57 (35.7967, 12.8827) -> (35.7967, 11)
  curve K58 (35.6767, 13.3738) -> (35.7967, 12.8827)
  curve K59 (35.2838, 13.5375) -> (35.6767, 13.3738)
  curve K60 (34.9004, 13.4284) -> (35.2838, 13.5375)
  curve K61 (34.6453, 13.1091) -> (34.9004, 13.4284)
  curve K62 (34.5662, 12.5034) -> (34.6453, 13.1091)
  line L58 (19.4202, 13.8104) -> (16.779, 13.8104)
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  dimension "d242" diameter = 7
  dimension "d243" diameter = 7
  dimension "d244" diameter = 7
  dimension "d245" diameter = 7
extrude "Extrusion63" cut sketch "Skizze43" against normal blind 3
extrude "Extrusion64" cut of existing geometry blind -0.2
extrude "Extrusion65" cut of existing geometry blind -0.2
sketch "Skizze44" plane through (45, 0, 0) normal (-1, 0, 0) x axis (0, -1, 0)
  line L1 (19.4202, 13.8104) -> (16.779, 13.8104)
  line L2 (19.4202, 13.352) -> (19.4202, 13.8104)
  line L3 (16.779, 13.352) -> (19.4202, 13.352)
  line L4 (16.779, 13.8104) -> (16.779, 13.352)
  line L5 (34.5662, 11) -> (34.5662, 12.5034)
  line L6 (34.075, 11) -> (34.5662, 11)
  line L7 (34.075, 13.8977) -> (34.075, 11)
  line L8 (34.5143, 13.8977) -> (34.075, 13.8977)
  line L9 (34.5143, 13.4911) -> (34.5143, 13.8977)
  curve K1 (34.8772, 13.8336) -> (34.5143, 13.4911)
  curve K2 (35.3929, 13.9632) -> (34.8772, 13.8336)
  curve K3 (35.9209, 13.8295) -> (35.3929, 13.9632)
  curve K4 (36.2115, 13.4557) -> (35.9209, 13.8295)
  curve K5 (37.1064, 13.9632) -> (36.2115, 13.4557)
  curve K6 (37.7694, 13.7244) -> (37.1064, 13.9632)
  curve K7 (38.0014, 12.9891) -> (37.7694, 13.7244)
  line L10 (38.0014, 11) -> (38.0014, 12.9891)
  line L11 (37.513, 11) -> (38.0014, 11)
  line L12 (37.513, 12.8254) -> (37.513, 11)
  curve K8 (37.4652, 13.2497) -> (37.513, 12.8254)
  curve K9 (37.292, 13.4584) -> (37.4652, 13.2497)
  curve K10 (36.9973, 13.5375) -> (37.292, 13.4584)
  curve K11 (36.4898, 13.3342) -> (36.9973, 13.5375)
  curve K12 (36.2879, 12.6835) -> (36.4898, 13.3342)
  line L13 (36.2879, 11) -> (36.2879, 12.6835)
  line L14 (35.7967, 11) -> (36.2879, 11)
  line L15 (35.7967, 12.8827) -> (35.7967, 11)
  curve K13 (35.6767, 13.3738) -> (35.7967, 12.8827)
  curve K14 (35.2838, 13.5375) -> (35.6767, 13.3738)
  curve K15 (34.9004, 13.4284) -> (35.2838, 13.5375)
  curve K16 (34.6453, 13.1091) -> (34.9004, 13.4284)
  curve K17 (34.5662, 12.5034) -> (34.6453, 13.1091)
  curve K18 (25.0177, 11.2374) -> (25.9086, 10.9318)
  curve K19 (24.6235, 12.0477) -> (25.0177, 11.2374)
  line L16 (25.1392, 12.0914) -> (24.6235, 12.0477)
  curve K20 (25.4052, 11.5252) -> (25.1392, 12.0914)
  curve K21 (25.9086, 11.3356) -> (25.4052, 11.5252)
  curve K22 (26.5089, 11.603) -> (25.9086, 11.3356)
  curve K23 (26.7544, 12.3124) -> (26.5089, 11.603)
  curve K24 (26.5184, 12.9754) -> (26.7544, 12.3124)
  curve K25 (25.9004, 13.2183) -> (26.5184, 12.9754)
  curve K26 (25.472, 13.1105) -> (25.9004, 13.2183)
  curve K27 (25.1719, 12.8308) -> (25.472, 13.1105)
  line L17 (24.7108, 12.8909) -> (25.1719, 12.8308)
  line L18 (25.0982, 14.9454) -> (24.7108, 12.8909)
  line L19 (27.0873, 14.9454) -> (25.0982, 14.9454)
  line L20 (27.0873, 14.4761) -> (27.0873, 14.9454)
  line L21 (25.4911, 14.4761) -> (27.0873, 14.4761)
  line L22 (25.2756, 13.4011) -> (25.4911, 14.4761)
  curve K28 (26.0314, 13.6521) -> (25.2756, 13.4011)
  curve K29 (26.9154, 13.2892) -> (26.0314, 13.6521)
  curve K30 (27.2756, 12.3561) -> (26.9154, 13.2892)
  curve K31 (26.9591, 11.4175) -> (27.2756, 12.3561)
  curve K32 (25.9086, 10.9318) -> (26.9591, 11.4175)
  line L23 (29.9113, 11) -> (29.9113, 12.5034)
  line L24 (29.4202, 11) -> (29.9113, 11)
  line L25 (29.4202, 13.8977) -> (29.4202, 11)
  line L26 (29.8595, 13.8977) -> (29.4202, 13.8977)
  line L27 (29.8595, 13.4911) -> (29.8595, 13.8977)
  curve K33 (30.2224, 13.8336) -> (29.8595, 13.4911)
  curve K34 (30.7381, 13.9632) -> (30.2224, 13.8336)
  curve K35 (31.266, 13.8295) -> (30.7381, 13.9632)
  curve K36 (31.5566, 13.4557) -> (31.266, 13.8295)
  curve K37 (32.4516, 13.9632) -> (31.5566, 13.4557)
  curve K38 (33.1146, 13.7244) -> (32.4516, 13.9632)
  curve K39 (33.3465, 12.9891) -> (33.1146, 13.7244)
  line L28 (33.3465, 11) -> (33.3465, 12.9891)
  line L29 (32.8581, 11) -> (33.3465, 11)
  line L30 (32.8581, 12.8254) -> (32.8581, 11)
  curve K40 (32.8104, 13.2497) -> (32.8581, 12.8254)
  curve K41 (32.6371, 13.4584) -> (32.8104, 13.2497)
  curve K42 (32.3424, 13.5375) -> (32.6371, 13.4584)
  curve K43 (31.8349, 13.3342) -> (32.3424, 13.5375)
  curve K44 (31.633, 12.6835) -> (31.8349, 13.3342)
  line L31 (31.633, 11) -> (31.633, 12.6835)
  line L32 (31.1419, 11) -> (31.633, 11)
  line L33 (31.1419, 12.8827) -> (31.1419, 11)
  curve K45 (31.0218, 13.3738) -> (31.1419, 12.8827)
  curve K46 (30.6289, 13.5375) -> (31.0218, 13.3738)
  curve K47 (30.2456, 13.4284) -> (30.6289, 13.5375)
  curve K48 (29.9905, 13.1091) -> (30.2456, 13.4284)
  curve K49 (29.9113, 12.5034) -> (29.9905, 13.1091)
  line L34 (23.3656, 15.0164) -> (23.0491, 15.0164)
  line L35 (23.3656, 11) -> (23.3656, 15.0164)
  line L36 (22.8745, 11) -> (23.3656, 11)
  line L37 (22.8745, 14.1296) -> (22.8745, 11)
  curve K50 (22.4093, 13.7913) -> (22.8745, 14.1296)
  curve K51 (21.8922, 13.5375) -> (22.4093, 13.7913)
  line L38 (21.8922, 14.0123) -> (21.8922, 13.5375)
  curve K52 (22.6126, 14.4816) -> (21.8922, 14.0123)
  curve K53 (23.0491, 15.0164) -> (22.6126, 14.4816)
  line L39 (19.4202, 12.5962) -> (16.779, 12.5962)
  line L40 (19.4202, 12.1378) -> (19.4202, 12.5962)
  line L41 (16.779, 12.1378) -> (19.4202, 12.1378)
  line L42 (16.779, 12.5962) -> (16.779, 12.1378)
  line L43 (14.5116, 11) -> (14.5116, 15)
  line L44 (14.0559, 11) -> (14.5116, 11)
  line L45 (14.0559, 11.3656) -> (14.0559, 11)
  curve K54 (13.2456, 10.9345) -> (14.0559, 11.3656)
  curve K55 (12.6085, 11.1255) -> (13.2456, 10.9345)
  curve K56 (12.1583, 11.6589) -> (12.6085, 11.1255)
  curve K57 (11.9986, 12.4461) -> (12.1583, 11.6589)
  curve K58 (12.1432, 13.2333) -> (11.9986, 12.4461)
  curve K59 (12.5771, 13.7749) -> (12.1432, 13.2333)
  curve K60 (13.2237, 13.9632) -> (12.5771, 13.7749)
  curve K61 (13.6903, 13.8527) -> (13.2237, 13.9632)
  curve K62 (14.0232, 13.5648) -> (13.6903, 13.8527)
  line L46 (14.0232, 15) -> (14.0232, 13.5648)
  line L47 (14.5116, 15) -> (14.0232, 15)
  line L48 (49.825, 51.35) -> (40.7094, 51.35)
  line L49 (49.825, 43) -> (49.825, 51.35)
  line L50 (51, 43) -> (49.825, 43)
  line L51 (51, 54) -> (51, 43)
  line L52 (46.9282, 54) -> (51, 54)
  line L53 (3, 60) -> (40, 60)
  line L54 (3, -2) -> (3, 60)
  line L55 (58, -2) -> (3, -2)
  line L56 (58, 8) -> (58, -2)
  line L57 (57, 8) -> (58, 8)
  line L58 (45, 39.55) -> (45, 20)
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  dimension "d252" diameter = 7
extrude "Extrusion66" add sketch "Skizze44" against normal blind 5
sketch "Skizze45" plane through (0, 0, 0) normal (0, -1, 0) x axis (1, 0, 0)
  line L1 (35.95, 30.55) -> (35.95, 34.9906)
  line L2 (29.7362, 30.55) -> (35.95, 30.55)
  line L3 (24.15, 50.35) -> (24.15, 33.3921)
  line L4 (35.95, 50.35) -> (24.15, 50.35)
  line L5 (35.95, 41.1094) -> (35.95, 50.35)
  line L6 (0, 20) -> (0, 41.3962)
  line L7 (-13, 8) -> (-12, 8)
  line L8 (-13, -2) -> (-13, 8)
  line L9 (42, -2) -> (-13, -2)
  line L10 (42, 59) -> (42, -2)
  line L11 (3.4189, 46.1396) -> (42, 59)
  arc A1 centre (37.65, 38.05) radius 3.5 clockwise from (35.95, 41.1094) to (35.95, 34.9906)
  arc A2 centre (22.15, 22.55) radius 11.025 clockwise from (29.7362, 30.55) to (24.15, 33.3921)
  circle C1 centre (37.65, 7.05) radius 3.5
  circle C2 centre (6.65, 38.05) radius 3.5
  circle C3 centre (6.65, 7.05) radius 3.5
  arc A3 centre (5, 41.3962) radius 5 clockwise from (0, 41.3962) to (3.4189, 46.1396)
  arc A4 centre (-12, 20) radius 12 clockwise from (0, 20) to (-12, 8)
  circle C4 centre (22.15, 22.55) radius 11.025
  circle C5 centre (22.15, 22.55) radius 3.5
  point P6 (29.7362, 30.55)
  concentric A2 C4
  coincident P6 C4
  concentric A2 C5
  dimension "d255" diameter C5 = 7
extrude "Extrusion67" add sketch "Skizze45" profile of A2 C4 C5 against normal blind 5
move "Verschieben16" TranslateX 0 TranslateY 0.1 TranslateZ 0
extrude "Extrusion45" cut of existing geometry blind -1.8
sketch "Skizze31" plane through (14, 0, 0) normal (-1, 0, 0) x axis (0, -1, 0)
  line L1 (22.15, 42.05) -> (22.15, 33.05)
  line L2 (19.15, 34.1959) -> (19.15, 40.9041)
  line L3 (22.15, -2) -> (22.15, 37.55)
  arc A1 centre (22.15, 37.55) radius 4.5 clockwise from (22.15, 33.05) to (19.15, 34.1959)
  arc A2 centre (22.15, 37.55) radius 4.5 clockwise from (19.15, 40.9041) to (22.15, 42.05)
  point P4 (22.15, 37.55)
  point P7 (22.15, 37.55)
  coincident P4 P7
  parallel L1 L3
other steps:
base_feature "Basiselement2" bodies "Nema 17-39", "Nema 17-39 (1)"
base_feature "Basiselement3"
base_feature "Basiselement4"
named bodies: "Nema 17-39", "Nema 17-39 (1)"

design "Leiterplatte 3 Laser"
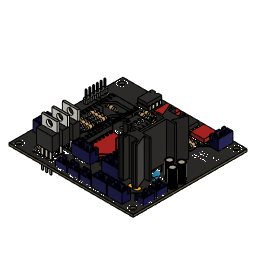
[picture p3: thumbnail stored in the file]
sketch "Skizze" plane through (0, 0, 0) normal (0, 0, 1) x axis (1, 0, 0)
  line L1 (85.07, 8.89) -> (0.96, 8.89)
  line L2 (85.07, 86.03) -> (85.07, 8.89)
  line L3 (0.96, 86.03) -> (85.07, 86.03)
  line L4 (0.96, 8.89) -> (0.96, 86.03)
  circle C1 centre (4.31, 82.05) radius 1.55
  circle C2 centre (4.31, 12.2) radius 1.55
  circle C3 centre (81.28, 82.55) radius 1.55
  circle C4 centre (81.28, 12.7) radius 1.55
  circle C5 centre (30.3, 56.2) radius 1.1
  circle C6 centre (60.2, 56.2) radius 1.1
  circle C7 centre (45.3, 27.7) radius 1.1
canvas "Ansichtsbereich1" bodies "Leiterplatte"
canvas "Ansichtsbereich2" bodies "Leiterplatte"
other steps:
base_feature "Basiselement1"
base_feature "Basiselement1"
base_feature "Basiselement1"
base_feature "Basiselement1"
base_feature "Basiselement1"
base_feature "Basiselement1"
base_feature "Basiselement1"
pcbextrude "Leiterplatte extrudieren1"
pcbextrude "Leiterplatte extrudieren1"
box_primitive "Grundkörper Quader1" DistanceX 18.262 DistanceY 38.341 DistanceZ 0.1 OffsetDistanceX 0 OffsetDistanceY 0
base_feature "Basiselement1"
base_feature "Basiselement1"
base_feature "Basiselement1"
base_feature "Basiselement1"
base_feature "Basiselement1"
base_feature "Basiselement1"
base_feature "Basiselement1"
base_feature "Basiselement1"
base_feature "Basiselement1"
base_feature "Basiselement1"
base_feature "Basiselement1"
box_primitive "Grundkörper Quader1" DistanceX 8.941 DistanceY 8.943 DistanceZ 2.458 OffsetDistanceX 0 OffsetDistanceY 0
box_primitive "Grundkörper Quader1" DistanceX 15.327 DistanceY 20.427 DistanceZ 0.1 OffsetDistanceX 0 OffsetDistanceY 0
pcbextrude "Leiterplatte extrudieren1" HoleDepth 1.606 HoleDiameter 2.3 TipAngle 10313.2
pcbextrude "Leiterplatte extrudieren1" HoleDepth 1.606 HoleDiameter 2.3 TipAngle 10313.2 HoleDepth 1.606 HoleDiameter 2.3 TipAngle 10313.2 HoleDepth 1.606 HoleDiameter 2.3 TipAngle 10313.2
extrude "Extrusion" sketch "Skizze" blind 1.5 HoleDepth 1.606 HoleDiameter 2.3 TipAngle 10313.2 bodies "Leiterplatte"
pcbextrude "Leiterplatte extrudieren1"
pcbextrude "Leiterplatte extrudieren2"
create_component "Komponente erstellen1"
create_component "Komponente erstellen2"
create_component "Komponente erstellen3"
create_component "Komponente erstellen4"
create_component "Komponente erstellen5"
create_component "Komponente erstellen6"
create_component "Komponente erstellen1"
create_component "Komponente erstellen2"
create_component "Komponente erstellen3"
create_component "Komponente erstellen1"
create_component "Komponente erstellen4"
create_component "Komponente erstellen1"
create_component "Komponente erstellen5"
create_component "Komponente erstellen1"
create_component "Komponente erstellen6"
create_component "Komponente erstellen7"
create_component "Komponente erstellen8"
create_component "Komponente erstellen9"
create_component "Komponente erstellen10"
create_component "Komponente erstellen1"
create_component "Komponente erstellen11"
create_component "Komponente erstellen1"
create_component "Komponente erstellen12"
create_component "Komponente erstellen13"
create_component "Komponente erstellen14"
as_built_joint "Bestand"
create_component "Komponente erstellen17"
create_component "Komponente erstellen1"
named bodies: "Leiterplatte"

design "Leiterplatte"
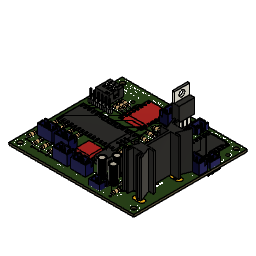
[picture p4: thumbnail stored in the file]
sketch "Skizze" plane through (0, 0, 0) normal (0, 0, 1) x axis (1, 0, 0)
  line L1 (85.07, 8.89) -> (0, 8.89)
  line L2 (85.07, 86.03) -> (85.07, 8.89)
  line L3 (0, 86.03) -> (85.07, 86.03)
  line L4 (0, 8.89) -> (0, 86.03)
  circle C1 centre (3.81, 82.55) radius 1.55
  circle C2 centre (3.81, 12.7) radius 1.55
  circle C3 centre (81.28, 82.55) radius 1.55
  circle C4 centre (81.28, 12.7) radius 1.55
  circle C5 centre (58.5, 73) radius 1
  circle C6 centre (18.5, 75) radius 1
  circle C7 centre (42, 70) radius 1
  circle C8 centre (82, 76) radius 1
canvas "Ansichtsbereich1" bodies "Leiterplatte"
canvas "Ansichtsbereich2" bodies "Leiterplatte"
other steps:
base_feature "Basiselement1"
base_feature "Basiselement1"
base_feature "Basiselement1"
base_feature "Basiselement1"
base_feature "Basiselement1"
base_feature "Basiselement1"
base_feature "Basiselement1"
pcbextrude "Leiterplatte extrudieren1"
pcbextrude "Leiterplatte extrudieren1"
box_primitive "Grundkörper Quader1" DistanceX 18.262 DistanceY 38.341 DistanceZ 0.1 OffsetDistanceX 0 OffsetDistanceY 0
base_feature "Basiselement1"
base_feature "Basiselement1"
base_feature "Basiselement1"
base_feature "Basiselement1"
base_feature "Basiselement1"
base_feature "Basiselement1"
base_feature "Basiselement1"
base_feature "Basiselement1"
base_feature "Basiselement1"
base_feature "Basiselement1"
base_feature "Basiselement1"
box_primitive "Grundkörper Quader1" DistanceX 8.941 DistanceY 8.943 DistanceZ 2.458 OffsetDistanceX 0 OffsetDistanceY 0
box_primitive "Grundkörper Quader1" DistanceX 15.327 DistanceY 20.427 DistanceZ 0.1 OffsetDistanceX 0 OffsetDistanceY 0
